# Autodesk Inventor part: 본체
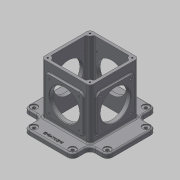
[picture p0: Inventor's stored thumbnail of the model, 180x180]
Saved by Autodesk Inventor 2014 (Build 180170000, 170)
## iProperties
Created: 2018-09
Part Number: 본체
Material: 일반
Document SubType Name: Modeling
Designer: mduedu
Density: 1 g/cm^3
Appearance: 기본값
Author: mduedu
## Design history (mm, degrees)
sketch "스케치1"
  geometry: L1 (90, 52.5)-(-90, 52.5); L2 (-90, 52.5)-(-90, -52.5); L3 (-90, -52.5)-(90, -52.5); L4 (90, -52.5)-(90, 52.5); L5 (90, 52.5)-(-90, -52.5); L6 (-90, 52.5)-(90, -52.5); L7 (-52.5, -90)-(52.5, -90); L8 (52.5, -90)-(52.5, 90); L9 (52.5, 90)-(-52.5, 90); L10 (-52.5, 90)-(-52.5, -90); L11 (-52.5, -90)-(52.5, 90); L12 (52.5, -90)-(-52.5, 90); 1 further point
  constraints: 24 end point, 4 midpoint, 4 parallel, 2 horizontal, 2 perpendicular
  dimensions: "d0" = 180 distance of L3.end L2.end; "d1" = 105 distance of L2.end L1.end; "d105" = 105 distance of L9.end L8.end; "d106" = 180 distance of L8.end L7.end
extrude "돌출1" new body sketch "스케치1" distance "d2" = 10; taper "d3" = 0 deg
fillet "모깎기16" dims "d107" = 11
sketch "스케치2"
  geometry: L1 (-52.5, -52.5)-(52.5, -52.5); L2 (52.5, -52.5)-(52.5, 52.5); L3 (52.5, 52.5)-(-52.5, 52.5); L4 (-52.5, 52.5)-(-52.5, -52.5); L5 (-52.5, -52.5)-(52.5, 52.5); L6 (52.5, -52.5)-(-52.5, 52.5); 1 further point
  constraints: 12 end point, 2 midpoint, 2 parallel, 1 horizontal, 1 perpendicular
  dimensions: "d4" = 105 distance of L3.end L2.end; "d5" = 105 distance of L2.end L1.end
extrude "돌출2" join sketch "스케치2" distance "d6" = 110; taper "d7" = 0 deg
sketch "스케치14"
  geometry: L1 (-52.5, 52.5)-(52.5, 52.5) reference; L2 (52.5, 52.5)-(52.5, -52.5) reference; L3 (52.5, -52.5)-(-52.5, -52.5) reference; L4 (-52.5, -52.5)-(-52.5, 52.5) reference; L5 (46.5, 46.5)-(-46.5, 46.5); L6 (-46.5, 46.5)-(-46.5, -46.5); L7 (-46.5, -46.5)-(46.5, -46.5); L8 (46.5, -46.5)-(46.5, 46.5); 1 further point
  constraints: 8 end point, 3 other
  dimensions: "d85" = 6 distance between parallel lines of L5 L1
extrude "돌출10" cut sketch "스케치14" stored distance "d86" = 10; taper "d87" = 0 deg
fillet "모깎기1" dims "d12" = 7
sketch "스케치15"
  geometry: A1 r 7 centre (-45.5, 45.5) between (-45.5, 52.5) and (-52.5, 45.5) reference; A2 r 7 centre (45.5, 45.5) between (52.5, 45.5) and (45.5, 52.5) reference; A3 r 7 centre (45.5, -45.5) between (45.5, -52.5) and (52.5, -45.5) reference; A4 r 7 centre (-45.5, -45.5) between (-52.5, -45.5) and (-45.5, -52.5) reference; 5 further points
  constraints: 4 coincident, 4 vertical alignment, 8 other
extrude "돌출11" join sketch "스케치15" stored distance "d88" = 10; taper "d89" = 0 deg
fillet "모깎기15" dims "d90" = 3
sketch "스케치6"
  geometry: L1 (50, 20)-(130, 20); L2 (130, 20)-(130, 100); L3 (130, 100)-(50, 100); L4 (50, 100)-(50, 20); L5 (50, 20)-(130, 100); L6 (130, 20)-(50, 100); L7 (0, 0)-(180, 0) reference; 4 further points
  constraints: 12 end point, 4 midpoint, 2 parallel, 1 horizontal, 1 perpendicular, 1 vertical alignment
  dimensions: "d25" = 80 distance of L3.end L2.end; "d26" = 80 distance of L2.end L1.end; "d27" = 60 distance of point (90, 0) point (90, 60)
extrude "돌출6" join sketch "스케치6" distance "d28" = 3; taper "d29" = 0 deg
fillet "모깎기7" dims "d30" = 8
sketch "스케치7"
  geometry: C1 r 32.5 at (90, 60); 1 further point
  constraints: 1 centre point, 1 vertical alignment
  dimensions: "d32" = 65 diameter of C1; "d33" = 60 distance of C1.centre point (90, 0)
extrude "돌출7" cut sketch "스케치7" stored distance "d34" = 3; taper "d35" = 0 deg
fillet "모깎기9" dims "d36" = 3
sketch "스케치8"
  geometry: L1 (5.5, 10)-(85.5, 10); L2 (85.5, 10)-(85.5, 90); L3 (85.5, 90)-(5.5, 90); L4 (5.5, 90)-(5.5, 10); L5 (5.5, 10)-(85.5, 90); L6 (85.5, 10)-(5.5, 90); L7 (-7, -10)-(98, -10) reference; C1 r 32.5 at (45.5, 50); 4 further points
  constraints: 12 end point, 4 midpoint, 2 parallel, 1 centre point, 1 coincident, 1 horizontal, 1 perpendicular, 1 vertical alignment
  dimensions: "d37" = 80 distance of L3.end L2.end; "d38" = 80 distance of L2.end L1.end; "d39" = 60 distance from line of point (45.5, 50) L7; "d40" = 65 diameter of C1
extrude "돌출8" join sketch "스케치8" distance "d41" = 3; taper "d42" = 0 deg
fillet "모깎기10" dims "d43" = 8
extrude "돌출9" cut sketch "스케치8" stored distance "d44" = 3; taper "d45" = 0 deg
fillet "모깎기11" dims "d46" = 3
sketch "스케치9"
  geometry: L1 (50, 92)-(50, 28) reference; L2 (58, 20)-(122, 20) reference; L3 (130, 28)-(130, 92) reference; L4 (122, 100)-(58, 100) reference; C1 r 32.5 at (90, 60) reference; A1 r 8 centre (58, 92) between (58, 100) and (50, 92) reference; A2 r 8 centre (58, 28) between (50, 28) and (58, 20) reference; A3 r 8 centre (122, 28) between (122, 20) and (130, 28) reference; A4 r 8 centre (122, 92) between (130, 92) and (122, 100) reference; 5 further points
  constraints: 4 coincident
hole "구멍1" sketch "스케치9" at (58, 92), (122, 92), (122, 28), (58, 28) diameter "d47" = 3.242; stored, may be unused: countersink angle "d51" = 90 deg, drill point angle "d53" = 118 deg; dims "d48" = 6, "d49" = 4, "d50" = 2, "d52" = 9
sketch "스케치10"
  geometry: L1 (13.5, 10)-(77.5, 10) reference; L2 (85.5, 18)-(85.5, 82) reference; L3 (77.5, 90)-(13.5, 90) reference; L4 (5.5, 82)-(5.5, 18) reference; C1 r 32.5 at (45.5, 50) reference; A1 r 8 centre (13.5, 18) between (5.5, 18) and (13.5, 10) reference; A2 r 8 centre (77.5, 18) between (77.5, 10) and (85.5, 18) reference; A3 r 8 centre (77.5, 82) between (85.5, 82) and (77.5, 90) reference; A4 r 8 centre (13.5, 82) between (13.5, 90) and (5.5, 82) reference; 5 further points
  constraints: 4 coincident
hole "구멍2" sketch "스케치10" at (13.5, 82), (77.5, 82), (77.5, 18), (13.5, 18) diameter "d54" = 3.242; stored, may be unused: countersink angle "d58" = 90 deg, drill point angle "d60" = 118 deg; dims "d55" = 6, "d56" = 4, "d57" = 2, "d59" = 9
fillet "모깎기12" dims "d68" = 11
sketch "스케치16"
  geometry: A1 r 11 centre (-79, 41.5) between (-79, 52.5) and (-90, 41.5) reference; A2 r 11 centre (-79, -41.5) between (-90, -41.5) and (-79, -52.5) reference; A3 r 11 centre (79, 41.5) between (90, 41.5) and (79, 52.5) reference; A4 r 11 centre (79, -41.5) between (79, -52.5) and (90, -41.5) reference; A5 r 11 centre (-41.5, 79) between (-41.5, 90) and (-52.5, 79) reference; A6 r 11 centre (41.5, 79) between (52.5, 79) and (41.5, 90) reference; A7 r 11 centre (41.5, -79) between (41.5, -90) and (52.5, -79) reference; A8 r 11 centre (-41.5, -79) between (-52.5, -79) and (-41.5, -90) reference; 9 further points
  constraints: 8 coincident
hole "구멍5" sketch "스케치16" at (-79, 41.5), (79, 41.5), (79, -41.5), (-79, -41.5), (41.5, 79), (-41.5, 79), (-41.5, -79), (41.5, -79) diameter "d91" = 6.6; stored, may be unused: countersink angle "d95" = 90 deg, drill point angle "d97" = 118 deg; dims "d92" = 6, "d93" = 15, "d94" = 2, "d96" = 8
fillet "모깎기13" dims "d77" = 3
chamfer "모따기1" distance "d79" = 1; stored, may be unused: second distance "d80" = 2, angle "d81" = 45 deg
sketch "스케치17"
  geometry: A1 r 7 centre (-45.5, 45.5) between (-45.5, 52.5) and (-52.5, 45.5) reference; A2 r 7 centre (-45.5, -45.5) between (-52.5, -45.5) and (-45.5, -52.5) reference; A3 r 7 centre (45.5, -45.5) between (45.5, -52.5) and (52.5, -45.5) reference; A4 r 7 centre (45.5, 45.5) between (52.5, 45.5) and (45.5, 52.5) reference; 5 further points
  constraints: 4 coincident
hole "구멍6" sketch "스케치17" at (-45.5, 45.5), (45.5, 45.5), (45.5, -45.5), (-45.5, -45.5) diameter "d98" = 3.242; stored, may be unused: countersink angle "d102" = 90 deg, drill point angle "d104" = 118 deg; dims "d99" = 8, "d100" = 15, "d101" = 2, "d103" = 10
sketch "스케치13"
  geometry: L1 (90, -41.5)-(90, 41.5) reference; 2 further points
  constraints: 1 horizontal alignment, 1 other
  dimensions: "d82" = 11 distance from line of point (79, 0) L1
feature "엠보싱1" sketch "스케치13" dims "d0" = 180, "d1" = 105, "d83" = 0.5, "d84" = 0
node "솔리드1"
mirror "대칭1"
mirror "대칭4"
mirror "대칭2"
mirror "대칭5"
node "투영된 루프2"
node "투영된 루프3"
node "투영된 루프6"
